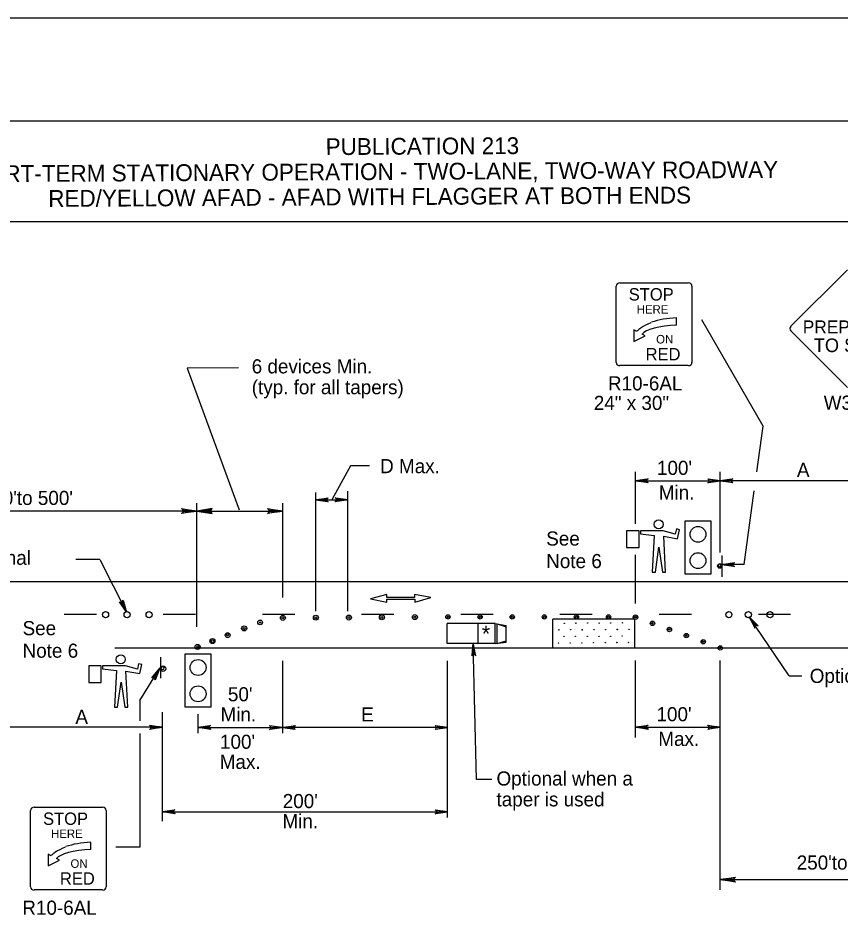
# Model space of a CAD drawing. Extents: x -14145 to -13521, y 30244 to 30661.
# Drawn here: x -13848.55 to -13836.31, y 30490.96 to 30504.31 of the extents above; entities that cross this region are included whole.
import ezdxf

# ---------------------------------------------------------------- set-up
doc = ezdxf.new("R2010")
doc.units = 0
for name, color, linetype in [('1', 7, 'Continuous'), ('10', 7, 'Continuous'), ('2', 7, 'Continuous'), ('3', 7, 'Continuous'), ('4', 7, 'Continuous'), ('61', 7, 'Continuous')]:
    doc.layers.add(name, color=color, linetype=linetype)

msp = doc.modelspace()

# ---------------------------------------------------------------- linework, layer by layer
at = {"layer": '1'}
for p, q in [((-13839.646, 30499.183), (-13839.646, 30500.319)), ((-13839.591, 30500.366), (-13838.573, 30500.366)), ((-13838.519, 30500.319), (-13838.519, 30499.183)), ((-13838.748, 30499.738), (-13838.75, 30499.849)), ((-13837.459, 30498.234), (-13838.37, 30499.816)), ((-13839.383, 30499.666), (-13839.383, 30499.495)), ((-13839.338, 30499.644), (-13839.383, 30499.666)), ((-13839.383, 30499.495), (-13839.212, 30499.581)), ((-13839.212, 30499.581), (-13839.259, 30499.604)), ((-13838.573, 30499.136), (-13839.591, 30499.136)), ((-13837.553, 30497.555), (-13837.459, 30498.234)), ((-13839.358, 30496.783), (-13839.358, 30497.555)), ((-13838.098, 30496.354), (-13838.098, 30497.555)), ((-13839.358, 30497.421), (-13838.098, 30497.421)), ((-13835.632, 30497.421), (-13838.098, 30497.421)), ((-13844.118, 30495.485), (-13844.118, 30497.249)), ((-13843.64, 30495.485), (-13843.64, 30497.267)), ((-13837.743, 30496.176), (-13837.591, 30497.275)), ((-13844.118, 30497.141), (-13843.64, 30497.141)), ((-13845.887, 30495.253), (-13845.887, 30497.09)), ((-13844.605, 30495.685), (-13844.605, 30497.09)), ((-13845.887, 30496.973), (-13850.398, 30496.973)), ((-13845.887, 30496.973), (-13844.605, 30496.973)), ((-13838.232, 30496.822), (-13838.623, 30496.822)), ((-13838.623, 30496.822), (-13838.623, 30496.04)), ((-13838.428, 30496.822), (-13838.428, 30496.822)), ((-13838.232, 30496.04), (-13838.232, 30496.822)), ((-13839.304, 30496.679), (-13839.492, 30496.679)), ((-13839.492, 30496.679), (-13839.492, 30496.429)), ((-13839.304, 30496.429), (-13839.304, 30496.679)), ((-13838.946, 30496.679), (-13839.286, 30496.679)), ((-13839.286, 30496.679), (-13839.286, 30496.635)), ((-13839.286, 30496.635), (-13839.08, 30496.609)), ((-13839.08, 30496.609), (-13839.108, 30496.063)), ((-13838.768, 30496.627), (-13838.946, 30496.679)), ((-13838.911, 30496.063), (-13838.937, 30496.599)), ((-13838.937, 30496.599), (-13838.732, 30496.561)), ((-13838.75, 30496.707), (-13838.768, 30496.627)), ((-13838.702, 30496.695), (-13838.75, 30496.707)), ((-13838.732, 30496.561), (-13838.702, 30496.695)), ((-13839.492, 30496.429), (-13839.304, 30496.429)), ((-13839.358, 30495.6), (-13839.358, 30496.319)), ((-13839.063, 30496.063), (-13839.009, 30496.437)), ((-13839.009, 30496.437), (-13838.956, 30496.063)), ((-13847.329, 30496.25), (-13847.686, 30496.25)), ((-13838.073, 30496.311), (-13838.073, 30495.993)), ((-13839.108, 30496.063), (-13839.063, 30496.063)), ((-13838.956, 30496.063), (-13838.911, 30496.063)), ((-13837.743, 30496.176), (-13838.073, 30496.176)), ((-13855.242, 30495.924), (-13829.67, 30495.924)), ((-13838.623, 30496.04), (-13838.232, 30496.04)), ((-13843.06, 30495.731), (-13843.302, 30495.665)), ((-13843.302, 30495.665), (-13843.058, 30495.619)), ((-13843.06, 30495.686), (-13843.06, 30495.731)), ((-13842.646, 30495.686), (-13843.06, 30495.686)), ((-13843.058, 30495.664), (-13842.644, 30495.664)), ((-13843.058, 30495.619), (-13843.058, 30495.664)), ((-13842.402, 30495.685), (-13842.646, 30495.731)), ((-13842.646, 30495.731), (-13842.646, 30495.686)), ((-13842.644, 30495.619), (-13842.402, 30495.685)), ((-13842.644, 30495.664), (-13842.644, 30495.619)), ((-13847.382, 30495.432), (-13847.862, 30495.432)), ((-13845.906, 30495.432), (-13846.386, 30495.432)), ((-13844.43, 30495.432), (-13844.91, 30495.432)), ((-13842.954, 30495.432), (-13843.434, 30495.432)), ((-13841.478, 30495.432), (-13841.958, 30495.432)), ((-13840.002, 30495.432), (-13840.482, 30495.432)), ((-13838.526, 30495.432), (-13839.006, 30495.432)), ((-13837.05, 30495.432), (-13837.53, 30495.432)), ((-13842.16, 30495.005), (-13842.16, 30495.3)), ((-13841.447, 30495.3), (-13842.16, 30495.3)), ((-13841.699, 30495.005), (-13841.699, 30495.3)), ((-13841.447, 30495.005), (-13841.447, 30495.3)), ((-13841.447, 30495.3), (-13841.281, 30495.272)), ((-13841.418, 30495.293), (-13841.281, 30495.25)), ((-13841.418, 30495.005), (-13841.418, 30495.293)), ((-13841.281, 30495.02), (-13841.281, 30495.272)), ((-13839.366, 30495.366), (-13840.59, 30495.366)), ((-13840.59, 30494.94), (-13840.59, 30495.366)), ((-13839.366, 30494.94), (-13839.366, 30495.366)), ((-13841.447, 30495.005), (-13842.16, 30495.005)), ((-13841.447, 30495.005), (-13841.281, 30495.02)), ((-13841.418, 30495.005), (-13841.281, 30495.041)), ((-13847.109, 30494.94), (-13829.67, 30494.94)), ((-13846.429, 30494.801), (-13846.429, 30494.489)), ((-13846.429, 30494.801), (-13846.429, 30494.489)), ((-13845.673, 30494.842), (-13846.063, 30494.842)), ((-13846.063, 30494.842), (-13846.063, 30494.06)), ((-13845.869, 30494.842), (-13845.869, 30494.842)), ((-13845.673, 30494.06), (-13845.673, 30494.842)), ((-13844.608, 30493.67), (-13844.608, 30494.744)), ((-13842.154, 30492.416), (-13842.154, 30494.744)), ((-13839.358, 30493.606), (-13839.358, 30494.752)), ((-13838.098, 30491.341), (-13838.098, 30494.752)), ((-13847.308, 30494.672), (-13847.496, 30494.672)), ((-13847.496, 30494.672), (-13847.496, 30494.422)), ((-13847.308, 30494.422), (-13847.308, 30494.672)), ((-13846.95, 30494.672), (-13847.29, 30494.672)), ((-13847.29, 30494.672), (-13847.29, 30494.628)), ((-13847.29, 30494.628), (-13847.084, 30494.602)), ((-13847.084, 30494.602), (-13847.112, 30494.056)), ((-13846.772, 30494.62), (-13846.95, 30494.672)), ((-13846.915, 30494.056), (-13846.941, 30494.592)), ((-13846.941, 30494.592), (-13846.736, 30494.554)), ((-13846.754, 30494.7), (-13846.772, 30494.62)), ((-13846.706, 30494.688), (-13846.754, 30494.7)), ((-13846.736, 30494.554), (-13846.706, 30494.688)), ((-13846.733, 30494.154), (-13846.435, 30494.634)), ((-13837.071, 30494.524), (-13836.882, 30494.524)), ((-13847.496, 30494.422), (-13847.308, 30494.422)), ((-13847.067, 30494.056), (-13847.013, 30494.43)), ((-13847.013, 30494.43), (-13846.96, 30494.056)), ((-13847.112, 30494.056), (-13847.067, 30494.056)), ((-13846.96, 30494.056), (-13846.915, 30494.056)), ((-13846.733, 30494.154), (-13846.733, 30493.851)), ((-13846.063, 30494.06), (-13845.673, 30494.06)), ((-13846.399, 30492.358), (-13846.399, 30493.982)), ((-13845.868, 30493.67), (-13845.868, 30493.954)), ((-13846.399, 30493.756), (-13848.865, 30493.756)), ((-13846.733, 30493.664), (-13846.733, 30491.973)), ((-13845.868, 30493.754), (-13844.608, 30493.754)), ((-13842.154, 30493.754), (-13844.608, 30493.754)), ((-13839.358, 30493.756), (-13838.098, 30493.756)), ((-13841.496, 30492.982), (-13841.724, 30492.982)), ((-13848.362, 30491.384), (-13848.362, 30492.52)), ((-13848.307, 30492.567), (-13847.289, 30492.567)), ((-13847.235, 30492.52), (-13847.235, 30491.384)), ((-13846.399, 30492.5), (-13842.154, 30492.5)), ((-13847.464, 30491.939), (-13847.466, 30492.05)), ((-13846.733, 30491.973), (-13847.094, 30491.973)), ((-13848.099, 30491.867), (-13848.099, 30491.696)), ((-13848.054, 30491.845), (-13848.099, 30491.867)), ((-13848.099, 30491.696), (-13847.928, 30491.782)), ((-13847.928, 30491.782), (-13847.975, 30491.805)), ((-13838.098, 30491.491), (-13833.845, 30491.491)), ((-13847.289, 30491.337), (-13848.307, 30491.337))]:
    msp.add_line(p, q, dxfattribs=at)
for points in [[(-13837.047, 30499.72), (-13836.205, 30500.561)], [(-13836.205, 30498.812), (-13837.047, 30499.654)], [(-13845.266, 30499.101), (-13846.029, 30499.1), (-13845.258, 30496.992)], [(-13843.316, 30497.643), (-13843.6, 30497.643), (-13843.879, 30497.141)], [(-13839.178, 30497.403), (-13839.19, 30497.415), (-13839.358, 30497.421), (-13839.178, 30497.403), (-13839.172, 30497.391), (-13839.358, 30497.421), (-13839.19, 30497.433), (-13839.184, 30497.445), (-13839.358, 30497.421), (-13839.172, 30497.451), (-13839.184, 30497.445)], [(-13838.278, 30497.445), (-13838.266, 30497.427), (-13838.098, 30497.421), (-13838.278, 30497.445), (-13838.284, 30497.451), (-13838.098, 30497.421), (-13838.266, 30497.415), (-13838.272, 30497.397), (-13838.098, 30497.421), (-13838.284, 30497.391), (-13838.272, 30497.397)], [(-13837.918, 30497.403), (-13837.924, 30497.415), (-13838.098, 30497.421), (-13837.918, 30497.403), (-13837.912, 30497.391), (-13838.098, 30497.421), (-13837.93, 30497.433), (-13837.924, 30497.445), (-13838.098, 30497.421), (-13837.912, 30497.451), (-13837.924, 30497.445)], [(-13843.944, 30497.117), (-13843.95, 30497.129), (-13844.118, 30497.141), (-13843.944, 30497.117), (-13843.932, 30497.111), (-13844.118, 30497.141), (-13843.95, 30497.147), (-13843.944, 30497.159), (-13844.118, 30497.141), (-13843.932, 30497.171), (-13843.944, 30497.159)], [(-13843.82, 30497.165), (-13843.814, 30497.153), (-13843.64, 30497.141), (-13843.82, 30497.165), (-13843.826, 30497.171), (-13843.64, 30497.141), (-13843.814, 30497.135), (-13843.82, 30497.123), (-13843.64, 30497.141), (-13843.826, 30497.111), (-13843.82, 30497.123)], [(-13847.329, 30496.25), (-13846.933, 30495.467)], [(-13837.899, 30496.152), (-13837.905, 30496.164), (-13838.073, 30496.176), (-13837.899, 30496.152), (-13837.887, 30496.146), (-13838.073, 30496.176), (-13837.905, 30496.182), (-13837.899, 30496.194), (-13838.073, 30496.176), (-13837.887, 30496.206), (-13837.899, 30496.194)], [(-13846.991, 30495.631), (-13846.998, 30495.62), (-13846.933, 30495.467), (-13846.991, 30495.631), (-13846.985, 30495.647), (-13846.933, 30495.467), (-13847.015, 30495.613), (-13847.028, 30495.613), (-13846.933, 30495.467), (-13847.039, 30495.623), (-13847.028, 30495.613)], [(-13837.071, 30494.524), (-13837.665, 30495.399)], [(-13837.55, 30495.269), (-13837.563, 30495.268), (-13837.665, 30495.399), (-13837.55, 30495.269), (-13837.533, 30495.266), (-13837.665, 30495.399), (-13837.577, 30495.256), (-13837.584, 30495.245), (-13837.665, 30495.399), (-13837.58, 30495.23), (-13837.584, 30495.245)], [(-13841.747, 30494.832), (-13841.759, 30494.84), (-13841.775, 30495.005), (-13841.747, 30494.832), (-13841.735, 30494.82), (-13841.775, 30495.005), (-13841.777, 30494.837), (-13841.789, 30494.831), (-13841.775, 30495.005), (-13841.794, 30494.817), (-13841.789, 30494.831)], [(-13841.724, 30492.982), (-13841.775, 30495.005)], [(-13846.548, 30494.492), (-13846.531, 30494.492), (-13846.435, 30494.634), (-13846.548, 30494.492), (-13846.557, 30494.492), (-13846.435, 30494.634), (-13846.515, 30494.483), (-13846.511, 30494.47), (-13846.435, 30494.634), (-13846.507, 30494.457), (-13846.511, 30494.47)], [(-13846.579, 30493.78), (-13846.573, 30493.762), (-13846.399, 30493.756), (-13846.579, 30493.78), (-13846.585, 30493.786), (-13846.399, 30493.756), (-13846.573, 30493.75), (-13846.579, 30493.732), (-13846.399, 30493.756), (-13846.585, 30493.726), (-13846.579, 30493.732)], [(-13845.688, 30493.736), (-13845.7, 30493.748), (-13845.868, 30493.754), (-13845.688, 30493.736), (-13845.682, 30493.724), (-13845.868, 30493.754), (-13845.7, 30493.766), (-13845.694, 30493.778), (-13845.868, 30493.754), (-13845.682, 30493.784), (-13845.694, 30493.778)], [(-13844.8, 30493.778), (-13844.788, 30493.76), (-13844.62, 30493.754), (-13844.8, 30493.778), (-13844.806, 30493.784), (-13844.62, 30493.754), (-13844.788, 30493.748), (-13844.794, 30493.73), (-13844.62, 30493.754), (-13844.806, 30493.724), (-13844.794, 30493.73)], [(-13844.428, 30493.73), (-13844.434, 30493.742), (-13844.608, 30493.754), (-13844.428, 30493.73), (-13844.422, 30493.724), (-13844.608, 30493.754), (-13844.434, 30493.76), (-13844.428, 30493.772), (-13844.608, 30493.754), (-13844.422, 30493.784), (-13844.428, 30493.772)], [(-13842.334, 30493.778), (-13842.328, 30493.76), (-13842.154, 30493.754), (-13842.334, 30493.778), (-13842.34, 30493.784), (-13842.154, 30493.754), (-13842.328, 30493.748), (-13842.334, 30493.73), (-13842.154, 30493.754), (-13842.34, 30493.724), (-13842.334, 30493.73)], [(-13839.178, 30493.738), (-13839.19, 30493.75), (-13839.358, 30493.756), (-13839.178, 30493.738), (-13839.172, 30493.726), (-13839.358, 30493.756), (-13839.19, 30493.768), (-13839.184, 30493.78), (-13839.358, 30493.756), (-13839.172, 30493.786), (-13839.184, 30493.78)], [(-13838.278, 30493.78), (-13838.266, 30493.762), (-13838.098, 30493.756), (-13838.278, 30493.78), (-13838.284, 30493.786), (-13838.098, 30493.756), (-13838.266, 30493.75), (-13838.272, 30493.732), (-13838.098, 30493.756), (-13838.284, 30493.726), (-13838.272, 30493.732)], [(-13846.219, 30492.482), (-13846.231, 30492.494), (-13846.399, 30492.5), (-13846.219, 30492.482), (-13846.213, 30492.47), (-13846.399, 30492.5), (-13846.231, 30492.512), (-13846.225, 30492.524), (-13846.399, 30492.5), (-13846.213, 30492.53), (-13846.225, 30492.524)], [(-13842.334, 30492.524), (-13842.322, 30492.506), (-13842.154, 30492.5), (-13842.334, 30492.524), (-13842.34, 30492.53), (-13842.154, 30492.5), (-13842.322, 30492.494), (-13842.328, 30492.476), (-13842.154, 30492.5), (-13842.34, 30492.47), (-13842.328, 30492.476)]]:
    msp.add_lwpolyline(points, dxfattribs=at)
for centre, radius in [((-13839.014, 30496.774), 0.0672), ((-13838.428, 30496.626), 0.118), ((-13838.428, 30496.235), 0.118), ((-13838.105, 30496.154), 0.0325), ((-13847.244, 30495.432), 0.0452), ((-13846.924, 30495.432), 0.0452), ((-13846.597, 30495.432), 0.0452), ((-13844.606, 30495.384), 0.037), ((-13844.607, 30495.383), 0.0149), ((-13844.115, 30495.387), 0.037), ((-13844.115, 30495.386), 0.0149), ((-13843.623, 30495.389), 0.037), ((-13843.624, 30495.389), 0.0149), ((-13843.132, 30495.392), 0.037), ((-13843.133, 30495.391), 0.0149), ((-13842.641, 30495.395), 0.037), ((-13842.641, 30495.394), 0.0149), ((-13842.149, 30495.398), 0.0321), ((-13842.148, 30495.396), 0.0143), ((-13841.671, 30495.398), 0.0321), ((-13841.67, 30495.396), 0.0143), ((-13841.193, 30495.398), 0.0321), ((-13841.192, 30495.396), 0.0143), ((-13840.715, 30495.398), 0.0321), ((-13840.714, 30495.396), 0.0143), ((-13840.237, 30495.398), 0.0321), ((-13840.236, 30495.396), 0.0143), ((-13839.759, 30495.398), 0.0321), ((-13839.758, 30495.396), 0.0143), ((-13839.358, 30495.394), 0.0331), ((-13839.359, 30495.395), 0.012), ((-13837.969, 30495.432), 0.0452), ((-13837.679, 30495.432), 0.0452), ((-13837.355, 30495.432), 0.0452), ((-13845.182, 30495.227), 0.038), ((-13844.945, 30495.317), 0.0346), ((-13844.944, 30495.313), 0.0101), ((-13840.419, 30495.304), 0.00272), ((-13840.246, 30495.305), 0.00272), ((-13840.072, 30495.307), 0.00272), ((-13839.898, 30495.305), 0.00272), ((-13839.726, 30495.308), 0.00272), ((-13839.551, 30495.31), 0.00272), ((-13839.106, 30495.303), 0.0331), ((-13839.107, 30495.304), 0.012), ((-13839.107, 30495.304), 0.012), ((-13845.428, 30495.126), 0.036), ((-13845.431, 30495.132), 0.0161), ((-13845.183, 30495.224), 0.0155), ((-13840.499, 30495.206), 0.00272), ((-13840.324, 30495.209), 0.00272), ((-13840.152, 30495.206), 0.00272), ((-13839.977, 30495.209), 0.00272), ((-13839.803, 30495.207), 0.00272), ((-13839.728, 30495.11), 0.00272), ((-13839.631, 30495.212), 0.00272), ((-13839.629, 30495.209), 0.00272), ((-13839.557, 30495.114), 0.00272), ((-13839.456, 30495.215), 0.00272), ((-13838.854, 30495.211), 0.0331), ((-13838.855, 30495.212), 0.012), ((-13838.602, 30495.12), 0.0331), ((-13838.603, 30495.121), 0.012), ((-13845.875, 30494.952), 0.0379), ((-13845.655, 30495.039), 0.037), ((-13845.654, 30495.037), 0.0194), ((-13840.504, 30495.011), 0.00272), ((-13840.424, 30495.108), 0.00272), ((-13840.329, 30495.012), 0.00272), ((-13840.253, 30495.108), 0.00272), ((-13840.156, 30495.012), 0.00272), ((-13840.076, 30495.109), 0.00272), ((-13839.982, 30495.013), 0.00272), ((-13839.903, 30495.109), 0.00272), ((-13839.808, 30495.014), 0.00272), ((-13839.636, 30495.017), 0.00272), ((-13839.635, 30495.014), 0.00272), ((-13839.462, 30495.018), 0.00272), ((-13838.35, 30495.029), 0.0331), ((-13838.351, 30495.029), 0.012), ((-13845.874, 30494.952), 0.014), ((-13838.097, 30494.937), 0.0331), ((-13838.099, 30494.938), 0.012), ((-13847.018, 30494.767), 0.0672), ((-13845.868, 30494.645), 0.118), ((-13846.389, 30494.628), 0.0408), ((-13845.868, 30494.254), 0.118)]:
    msp.add_circle(centre, radius, dxfattribs=at)
for centre, radius, start, end in [((-13837.014, 30499.687), 0.0465, 135, 224.9684), ((-13838.106, 30496.165), 0.0214, 355.7499, 350.479), ((-13846.394, 30494.636), 0.0214, 189.521, 184.2501)]:
    msp.add_arc(centre, radius, start, end, dxfattribs=at)
for centre, major_axis, ratio, start_param, end_param in [((-13839.591, 30500.318), (-0.0541, 0), 0.866667, 4.712389, 6.283185), ((-13838.572, 30500.318), (-0.0541, 0), 0.866667, 3.141593, 4.712389), ((-13838.706, 30499.626), (0.626, 0.024), 0.356316, 1.625555, 2.277861), ((-13838.739, 30499.6), (0.626, 0.024), 0.356316, 2.688881, 2.833949), ((-13839.097, 30499.501), (-0.29, 0), 0.866667, 5.239865, 5.534055), ((-13838.714, 30499.838), (0.632, 0.211), 0.13767, 2.24751, 2.61166), ((-13838.739, 30499.6), (0.526, 0.021), 0.259792, 1.574563, 2.966983), ((-13839.591, 30499.182), (0.0541, 0), 0.866667, 3.141593, 4.712389), ((-13838.572, 30499.182), (0.0541, 0), 0.866667, 4.712389, 6.283185), ((-13848.307, 30492.519), (-0.0541, 0), 0.866667, 4.712389, 6.283185), ((-13847.289, 30492.519), (-0.0541, 0), 0.866667, 3.141593, 4.712389), ((-13847.423, 30491.827), (0.626, 0.024), 0.356316, 1.625555, 2.277861), ((-13847.814, 30491.702), (-0.29, 0), 0.866667, 5.239865, 5.534055), ((-13847.43, 30492.039), (0.632, 0.211), 0.13767, 2.24751, 2.61166), ((-13847.455, 30491.801), (0.526, 0.021), 0.259792, 1.574563, 2.966983), ((-13847.455, 30491.801), (0.626, 0.024), 0.356316, 2.688881, 2.833949), ((-13848.307, 30491.383), (0.0541, 0), 0.866667, 3.141593, 4.712389), ((-13847.289, 30491.383), (0.0541, 0), 0.866667, 4.712389, 6.283185)]:
    msp.add_ellipse(centre, major_axis=major_axis, ratio=ratio, start_param=start_param, end_param=end_param, dxfattribs=at)
at = {"layer": '10'}
for p, q in [((-13857.874, 30502.777), (-13826.422, 30502.777)), ((-13857.874, 30501.277), (-13826.422, 30501.277))]:
    msp.add_line(p, q, dxfattribs=at)
at = {"layer": '3'}
for points in [[(-13846.105, 30497), (-13846.097, 30496.985), (-13845.887, 30496.973), (-13846.105, 30497), (-13846.116, 30497.01), (-13845.887, 30496.973), (-13846.097, 30496.963), (-13846.104, 30496.947), (-13845.887, 30496.973), (-13846.116, 30496.937), (-13846.104, 30496.947)], [(-13845.669, 30497), (-13845.677, 30496.985), (-13845.887, 30496.973), (-13845.669, 30497), (-13845.658, 30497.01), (-13845.887, 30496.973), (-13845.677, 30496.963), (-13845.67, 30496.947), (-13845.887, 30496.973), (-13845.658, 30496.937), (-13845.67, 30496.947)], [(-13844.823, 30497), (-13844.815, 30496.985), (-13844.605, 30496.973), (-13844.823, 30497), (-13844.834, 30497.01), (-13844.605, 30496.973), (-13844.815, 30496.963), (-13844.822, 30496.947), (-13844.605, 30496.973), (-13844.834, 30496.937), (-13844.822, 30496.947)], [(-13837.88, 30491.464), (-13837.888, 30491.479), (-13838.098, 30491.491), (-13837.88, 30491.464), (-13837.869, 30491.454), (-13838.098, 30491.491), (-13837.888, 30491.501), (-13837.88, 30491.517), (-13838.098, 30491.491), (-13837.869, 30491.527), (-13837.88, 30491.517)]]:
    msp.add_lwpolyline(points, dxfattribs=at)
at = {"layer": '61'}
msp.add_lwpolyline([(-13858.174, 30504.307), (-13825.174, 30504.307), (-13825.174, 30478.807), (-13858.174, 30478.807)], close=True, dxfattribs=at)

# ---------------------------------------------------------------- texts
at = {"layer": '1'}
for s, height, p in [('STOP', 0.1838, (-13839.459, 30500.104)), ('HERE', 0.1268, (-13839.34, 30499.908)), ('PREPARED', 0.1925, (-13836.869, 30499.615)), ('ON', 0.1268, (-13839.051, 30499.465)), ('TO STOP', 0.2024, (-13836.705, 30499.337)), ('RED', 0.1838, (-13839.208, 30499.214)), ('See', 0.21, (-13840.687, 30496.459)), ('Note 6', 0.21, (-13840.687, 30496.124)), ('See', 0.21, (-13848.48, 30495.126)), ('Note 6', 0.21, (-13848.48, 30494.791)), ('STOP', 0.1838, (-13848.175, 30492.305)), ('HERE', 0.1268, (-13848.056, 30492.109)), ('ON', 0.1268, (-13847.767, 30491.666)), ('RED', 0.1838, (-13847.924, 30491.415))]:
    msp.add_text(s, height=height, dxfattribs=at).set_placement(p)
msp.add_text('*', height=0.238, rotation=0.7233, dxfattribs=at).set_placement((-13841.643, 30495.028))
at = {"layer": '2'}
for s, p in [('6 devices Min.', (-13845.07, 30499.02)), ('(typ. for all tapers)', (-13845.07, 30498.71))]:
    msp.add_text(s, height=0.21, rotation=360, dxfattribs=at).set_placement(p)
for s, p in [('R10-6AL', (-13839.768, 30498.767)), ('24" x 30"', (-13839.979, 30498.476)), ('W3-4', (-13836.557, 30498.479)), ('D Max.', (-13843.159, 30497.536)), ("100'", (-13839.039, 30497.51)), ('A', (-13836.956, 30497.481)), ("250'to 500'", (-13849.087, 30497.063)), ('Min.', (-13839.012, 30497.143)), ('Optional', (-13849.402, 30496.173)), ('Optional', (-13836.765, 30494.416)), ("50'", (-13845.424, 30494.143)), ('Min.', (-13845.534, 30493.844)), ('E', (-13843.441, 30493.843)), ("100'", (-13839.046, 30493.846)), ('A', (-13847.694, 30493.807)), ("100'", (-13845.542, 30493.436)), ('Max.', (-13839.019, 30493.479)), ('Max.', (-13845.546, 30493.137)), ('Optional when a', (-13841.427, 30492.89)), ("200'", (-13844.608, 30492.554)), ('taper is used', (-13841.427, 30492.58)), ('Min.', (-13844.612, 30492.255)), ("250'to 500'", (-13836.959, 30491.64)), ('R10-6AL', (-13848.484, 30490.968))]:
    msp.add_text(s, height=0.21, dxfattribs=at).set_placement(p)
at = {"layer": '4'}
for s, p in [('PUBLICATION 213', (-13843.969, 30502.267)), ('SHORT-TERM STATIONARY OPERATION - TWO-LANE, TWO-WAY ROADWAY', (-13849.475, 30501.862)), ('RED/YELLOW AFAD - AFAD WITH FLAGGER AT BOTH ENDS', (-13848.097, 30501.496))]:
    msp.add_text(s, height=0.25, rotation=0.31, dxfattribs=at).set_placement(p)

doc.saveas('drawing.dxf')
